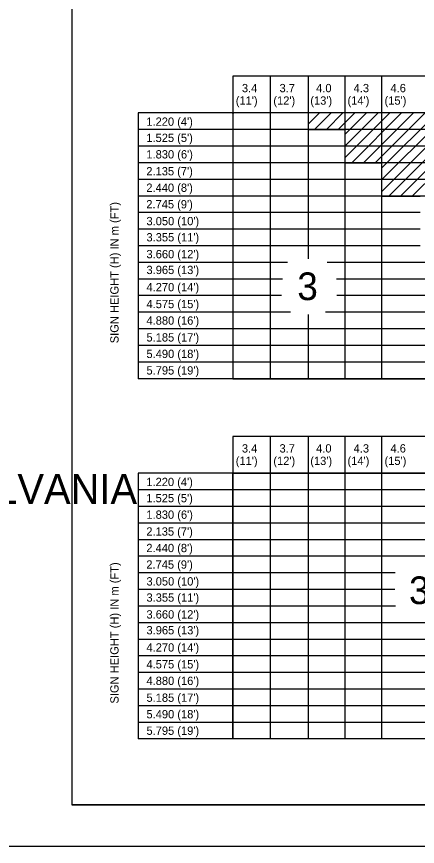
# Model space of a CAD drawing. Extents: x 637580 to 641008, y 294594 to 295782.
# Drawn here: x 639282.3 to 639427.3, y 294593.6 to 294893.4 of the extents above; entities that cross this region are included whole.
import ezdxf

# ---------------------------------------------------------------- set-up
doc = ezdxf.new("R2010")
doc.units = 0
for name, color, linetype in [('1', 7, 'Continuous'), ('2', 7, 'Continuous'), ('PLT-BNDY', 7, 'Continuous')]:
    doc.layers.add(name, color=color, linetype=linetype)

msp = doc.modelspace()

# ---------------------------------------------------------------- linework, layer by layer
at = {"layer": '1'}
for p, q in [((639302.31, 295172.63), (639302.31, 294608.63)), ((640088.31, 294608.63), (639302.31, 294608.63)), ((639302.31, 294608.63), (639888.31, 294608.63))]:
    msp.add_line(p, q, dxfattribs=at)
at = {"layer": '2'}
for p, q in [((639680.91, 294871.85), (639360.51, 294871.85)), ((639360.51, 294871.85), (639360.51, 294762.59)), ((639374.02, 294871.85), (639374.02, 294762.59)), ((639387.78, 294871.85), (639387.78, 294805.85)), ((639401.03, 294871.85), (639401.03, 294762.59)), ((639414.29, 294871.85), (639414.29, 294762.59)), ((639326.28, 294858.59), (639326.28, 294762.59)), ((639360.51, 294858.59), (639326.28, 294858.59)), ((639360.51, 294858.19), (639360.92, 294858.59)), ((639387.78, 294858.59), (639360.51, 294858.59)), ((639360.51, 294858.59), (639360.51, 294762.59)), ((639393.34, 294858.64), (639387.78, 294858.59)), ((639387.78, 294858.59), (639387.78, 294852.59)), ((639387.78, 294854.56), (639391.81, 294858.59)), ((639390.05, 294852.59), (639396.1, 294858.64)), ((639455.06, 294858.59), (639393.34, 294858.64)), ((639394.34, 294852.64), (639400.34, 294858.64)), ((639398.54, 294852.59), (639404.58, 294858.64)), ((639401.03, 294850.85), (639408.82, 294858.64)), ((639401.03, 294846.61), (639413.07, 294858.64)), ((639401.03, 294842.36), (639417.31, 294858.64)), ((639403.51, 294840.6), (639421.55, 294858.64)), ((639407.76, 294840.6), (639425.79, 294858.64)), ((639412, 294840.6), (639430.04, 294858.64)), ((639414.28, 294838.64), (639434.28, 294858.64)), ((639414.28, 294834.4), (639438.48, 294858.59)), ((639414.28, 294830.15), (639442.72, 294858.59)), ((639416.99, 294828.62), (639446.96, 294858.59)), ((639421.23, 294828.62), (639451.2, 294858.59)), ((639425.48, 294828.62), (639455.06, 294858.21)), ((639641.9, 294852.59), (639326.28, 294852.59)), ((639387.78, 294852.59), (639401.03, 294852.59)), ((639401.03, 294852.59), (639401.03, 294840.6)), ((639654.9, 294846.59), (639326.28, 294846.59)), ((639654.9, 294840.59), (639326.28, 294840.59)), ((639401.03, 294840.6), (639414.29, 294840.6)), ((639414.29, 294840.6), (639414.29, 294828.59)), ((639667.91, 294834.59), (639326.28, 294834.59)), ((639667.91, 294828.59), (639326.28, 294828.59)), ((639414.29, 294828.59), (639428.3, 294828.59)), ((639428.3, 294822.59), (639326.28, 294822.59)), ((639428.3, 294816.59), (639326.28, 294816.59)), ((639428.3, 294810.59), (639326.28, 294810.59)), ((639380.32, 294804.59), (639326.28, 294804.59)), ((639680.91, 294804.59), (639394.62, 294804.59)), ((639378.48, 294798.59), (639326.28, 294798.59)), ((639680.91, 294798.59), (639397.99, 294798.59)), ((639378.07, 294792.59), (639326.28, 294792.59)), ((639680.91, 294792.59), (639398.13, 294792.59)), ((639381.39, 294786.59), (639326.28, 294786.59)), ((639387.78, 294785.78), (639387.78, 294762.59)), ((639680.91, 294786.59), (639393.98, 294786.59)), ((639680.91, 294780.59), (639326.28, 294780.59)), ((639680.91, 294774.59), (639326.28, 294774.59)), ((639680.91, 294768.59), (639326.28, 294768.59)), ((639680.91, 294762.59), (639326.28, 294762.59)), ((639360.51, 294762.59), (639495.33, 294762.59)), ((639680.91, 294741.69), (639360.51, 294741.69)), ((639360.51, 294741.69), (639360.51, 294632.43)), ((639374.02, 294741.69), (639374.02, 294632.43)), ((639387.78, 294741.69), (639387.78, 294632.43)), ((639401.03, 294741.69), (639401.03, 294632.43)), ((639414.29, 294741.69), (639414.29, 294632.43)), ((639680.91, 294728.43), (639326.28, 294728.43)), ((639326.28, 294728.43), (639326.28, 294632.43)), ((639360.51, 294632.43), (639360.51, 294728.43)), ((639360.51, 294728.43), (639455.01, 294728.25)), ((639641.9, 294722.43), (639326.28, 294722.43)), ((639654.9, 294716.43), (639326.28, 294716.43)), ((639654.9, 294710.43), (639326.28, 294710.43)), ((639667.91, 294704.43), (639326.28, 294704.43)), ((639667.91, 294698.43), (639326.28, 294698.43)), ((639419.17, 294692.43), (639326.28, 294692.43)), ((639419.11, 294686.43), (639326.28, 294686.43)), ((639419.3, 294680.43), (639326.28, 294680.43)), ((639387.78, 294674.43), (639326.28, 294674.43)), ((639680.91, 294674.43), (639387.78, 294674.43)), ((639387.78, 294668.43), (639326.28, 294668.43)), ((639680.91, 294668.43), (639387.78, 294668.43)), ((639387.78, 294662.43), (639326.28, 294662.43)), ((639680.91, 294662.43), (639387.78, 294662.43)), ((639387.78, 294656.43), (639326.28, 294656.43)), ((639680.91, 294656.43), (639387.78, 294656.43)), ((639680.91, 294650.43), (639326.28, 294650.43)), ((639680.91, 294644.43), (639326.28, 294644.43)), ((639680.91, 294638.43), (639326.28, 294638.43)), ((639680.91, 294632.43), (639326.28, 294632.43)), ((639563.62, 294632.43), (639360.51, 294632.43))]:
    msp.add_line(p, q, dxfattribs=at)
at = {"layer": 'PLT-BNDY'}
msp.add_lwpolyline([(639262.31, 295187.63), (640103.31, 295187.63), (640103.31, 294593.63), (639262.31, 294593.63)], close=True, dxfattribs=at)

# ---------------------------------------------------------------- texts
at = {"layer": '1'}
msp.add_text('COMMONWEALTH OF PENNSYLVANIA', height=10.7828, dxfattribs=at).set_placement((639059.9, 294717.36))
at = {"layer": '2'}
for s, height, p in [('3.4', 3, (639363.79, 294866.08)), ('3.7', 3, (639377.39, 294866.08)), ('4.0', 3, (639390.63, 294866.08)), ('4.3', 3, (639404.19, 294866.08)), ('4.6', 3, (639417.51, 294866.08)), ("(11')", 3, (639361.56, 294861.58)), ("(12')", 3, (639375.16, 294861.58)), ("(13')", 3, (639388.52, 294861.58)), ("(14')", 3, (639401.97, 294861.58)), ("(15')", 3, (639415.36, 294861.58)), ("1.220 (4')", 3, (639329.23, 294853.96)), ("1.525 (5')", 3, (639329.23, 294848.11)), ("1.830 (6')", 3, (639329.25, 294842.15)), ("2.135 (7')", 3, (639329.23, 294836.05)), ("2.440 (8')", 3, (639329.23, 294830.09)), ("2.745 (9')", 3, (639329.22, 294824.12)), ("3.050 (10')", 3, (639329.28, 294818.03)), ("3.355 (11')", 3, (639329.28, 294812.19)), ("3.660 (12')", 3, (639329.28, 294806.1)), ("3.965 (13')", 3, (639329.28, 294800.39)), ('3', 10, (639383.81, 294790.98)), ("4.270 (14')", 3, (639329.28, 294794.17)), ("4.575 (15')", 3, (639329.28, 294788.08)), ("4.880 (16')", 3, (639329.28, 294782.11)), ("5.185 (17')", 3, (639329.28, 294776.02)), ("5.490 (18')", 3, (639329.28, 294770.06)), ("5.795 (19')", 3, (639329.28, 294764.09)), ('3.4', 3, (639363.79, 294735.92)), ('3.7', 3, (639377.39, 294735.92)), ('4.0', 3, (639390.63, 294735.92)), ('4.3', 3, (639404.19, 294735.92)), ('4.6', 3, (639417.51, 294735.92)), ("(11')", 3, (639361.56, 294731.42)), ("(12')", 3, (639375.16, 294731.42)), ("(13')", 3, (639388.52, 294731.42)), ("(14')", 3, (639401.97, 294731.42)), ("(15')", 3, (639415.36, 294731.42)), ("1.220 (4')", 3, (639329.23, 294723.8)), ("1.525 (5')", 3, (639329.23, 294717.95)), ("1.830 (6')", 3, (639329.25, 294711.98)), ("2.135 (7')", 3, (639329.23, 294705.89)), ("2.440 (8')", 3, (639329.23, 294699.93)), ("2.745 (9')", 3, (639329.22, 294693.96)), ("3.050 (10')", 3, (639329.28, 294687.87)), ('3', 10, (639424.21, 294681.16)), ("3.355 (11')", 3, (639329.28, 294682.03)), ("3.660 (12')", 3, (639329.28, 294675.94)), ("3.965 (13')", 3, (639329.28, 294670.23)), ("4.270 (14')", 3, (639329.28, 294664.01)), ("4.575 (15')", 3, (639329.28, 294657.92)), ("4.880 (16')", 3, (639329.28, 294651.95)), ("5.185 (17')", 3, (639329.28, 294645.86)), ("5.490 (18')", 3, (639329.28, 294639.9)), ("5.795 (19')", 3, (639329.28, 294633.93))]:
    msp.add_text(s, height=height, dxfattribs=at).set_placement(p)
for p in [(639319.19, 294775.39), (639319.19, 294645.23)]:
    msp.add_text('SIGN HEIGHT (H) IN m (FT)', height=3, rotation=90, dxfattribs=at).set_placement(p)

doc.saveas('drawing.dxf')
